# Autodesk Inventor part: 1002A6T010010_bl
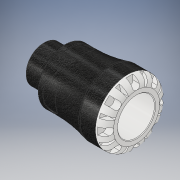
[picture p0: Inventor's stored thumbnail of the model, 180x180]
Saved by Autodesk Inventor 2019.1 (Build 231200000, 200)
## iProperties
Created: 2016-12
Part Number: 1002A6T010010_bl
Material: PVC-Piping
Description: PLASSON MALE ADAPTOR 1''IPS x 1''NPT SERIES 1
Document SubType Name: Modeling
Designer: KIM
Mass: 61.7504 g
Surface Area: 140.097 cm^2
Volume: 44.1074 cm^3
Density: 1.4 g/cm^3
Appearance: Black Cast
Author: KIM
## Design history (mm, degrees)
derived "1002A.ipt"
feature "Solid1::1002A.ipt" dims "ScaleForDerivedMember" = 10
tag "TaggingFeature1"
body "Solid1"
other parameters: "d0" = 84.074 [user parameter], "d1" = 22.72284 [user parameter], "d2" = 33.3 [user parameter], "d3" = 41.625 [user parameter], "d4" = 57.912 [user parameter], "d6" = 54.102 [user parameter], "d8" = 49.2252 [user parameter], "d13" = 6.5148 [user parameter], "d14" = 6.5148 [user parameter], "d15" = 0 [user parameter], "d17" = 360 deg [user parameter], "d19" = 8 deg [user parameter], "d20" = 0.666 [user parameter], "d21" = 0.666 [user parameter], "d22" = 8 deg [user parameter], "d24" = 0 [user parameter], "d26" = 360 deg [user parameter], "d32" = 0.925 [user parameter], "d33" = 5.7912 [user parameter], "d34" = 33.249 [user parameter], "d35" = 4.1625 [user parameter], "d38" = 19.05 [user parameter], "d39" = 0.99747 [user parameter], "d42" = 11.655 [user parameter], "d43" = 7.659 [user parameter], "d45" = 12.76901 [user parameter], "d46" = 0 [user parameter], "d59" = 360 deg [user parameter], "d61" = 9.90675 [user parameter], "d62" = 0.666 [user parameter], "d64" = 0 [user parameter], "d65" = 0.57912 [user parameter], "d_" = 33.3 [user parameter], "E_" = 57.912 [user parameter], "H_" = 84.074 [user parameter], "l_" = 54.102 [user parameter], "R_" = 33.249 [user parameter], "l_2" = 19.05 [user parameter], "d9" = 8.1435 [user parameter], "d11" = 57.912 [user parameter], "d12" = 41.625 [user parameter]
